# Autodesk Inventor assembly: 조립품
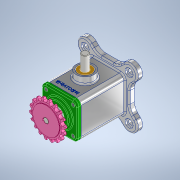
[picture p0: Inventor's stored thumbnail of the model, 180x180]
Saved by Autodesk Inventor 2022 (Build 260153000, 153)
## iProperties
Created: 2022-05
Part Number: 조립품
Document SubType Name: Assembly
Designer: Admin
Author: Admin
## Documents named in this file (11)
- C:\Users\Admin\Desktop\720509V1008\조립품.iam
- C:\Users\Admin\Desktop\720509V1008\본체.ipt
- C:\Users\Admin\Desktop\720509V1008\커버.ipt
- C:\Users\Admin\Desktop\720509V1008\베어링 6203.ipt
- C:\Users\Admin\Desktop\720509V1008\편심축.ipt
- C:\Users\Admin\Desktop\720509V1008\오일 실.ipt
- C:\Users\Admin\Desktop\720509V1008\부시.ipt
- C:\Users\Admin\Desktop\720509V1008\슬라이더.ipt
- C:\Users\Admin\Desktop\720509V1008\키 4 x 4 x 14.ipt
- C:\Users\Admin\Desktop\720509V1008\스프로킷.ipt
- C:\Users\Admin\Desktop\720509V1008\볼트 M4.ipt
